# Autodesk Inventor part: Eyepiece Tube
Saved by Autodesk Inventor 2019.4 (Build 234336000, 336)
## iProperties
Created: 2020-09
Part Number: Eyepiece Tube
Material: Generic
Document SubType Name: Modeling
Designer: Administrator
Density: 1 g/cm^3
Appearance: Default
Title: Eyepiece Tube
Author: Administrator
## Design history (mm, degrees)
feature "Body1"
body "Solid1"
